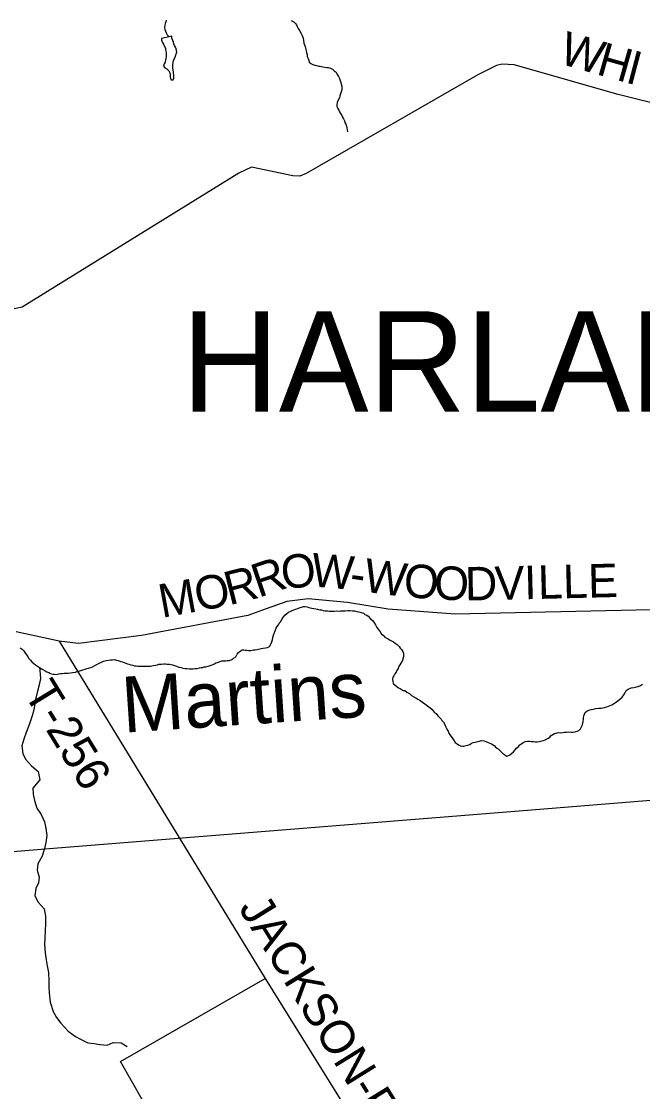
# Model space of a CAD drawing. Extents: x 1310247 to 1664935, y 284496 to 704931.
# Drawn here: x 1521928 to 1527488, y 468911 to 478494 of the extents above; entities that cross this region are included whole.
import ezdxf

# ---------------------------------------------------------------- set-up
doc = ezdxf.new("R2010")
doc.units = 0
for name, color, linetype in [('GM_X_Airport_Location_Class_2', 7, 'Continuous'), ('GM_X_County_Road_Text', 7, 'Continuous'), ('GM_X_County_Subdivision_Text', 7, 'Continuous'), ('GM_X_Minor_Lake_Text', 7, 'Continuous'), ('GM_X_Minor_River', 7, 'Continuous'), ('GM_X_Minor_River_Text', 7, 'Continuous'), ('GM_X_State_Route', 7, 'Continuous'), ('GM_X_Township_Road', 7, 'Continuous'), ('GM_X_Township_Subdivision', 7, 'Continuous')]:
    doc.layers.add(name, color=color, linetype=linetype)

msp = doc.modelspace()

# ---------------------------------------------------------------- linework, layer by layer
at = {"layer": 'GM_X_County_Road_Text'}
for points in [[(1527736.4, 477723.4), (1527268.2, 477838.9), (1526338.4, 478104.1), (1526232, 478109.7), (1526181.6, 478098.5), (1526013.6, 478014.9), (1524475.3, 477132.2), (1524418.6, 477107), (1524356.4, 477110), (1523988.1, 477187.9), (1523872.7, 477135.5), (1521933.8, 475934.2), (1521863.3, 475919.2)], [(1529754.6, 471722.4), (1529016.4, 472240.5), (1527703.6, 473187.4), (1527659.8, 473216.1), (1527563.6, 473225.7), (1525811.4, 473184.7), (1525209.6, 473232.1), (1524847, 473289.8), (1524496, 473323.4), (1524304.8, 473298.2), (1524119, 473232.9), (1523953.3, 473173.3), (1523002.5, 472995.5), (1522438.9, 472922.1), (1522264.5, 472942.8), (1521880.2, 473029)]]:
    msp.add_lwpolyline(points, dxfattribs=at)
at = {"layer": 'GM_X_County_Subdivision_Text'}
for points in [[(1522264.5, 472942.8), (1524109.1, 469924), (1526335.9, 466341.4)], [(1523319, 469469.4), (1524109.1, 469924)], [(1519694.9, 466699.1), (1522985.1, 468700), (1523036.2, 468753.3), (1523011.4, 468833.9), (1522816, 469179.9), (1523318.3, 469469), (1523319, 469469.4)]]:
    msp.add_lwpolyline(points, dxfattribs=at)
at = {"layer": 'GM_X_Minor_River'}
for points in [[(1523250.7, 478355.1), (1523180.5, 478340.8)], [(1523180.5, 478340.8), (1523182.1, 478324.7), (1523189.7, 478306.5), (1523199.3, 478290.2), (1523205, 478276), (1523216.5, 478253.6), (1523218.2, 478239.6), (1523223.6, 478215.3), (1523223.2, 478201.3), (1523222.7, 478179.2), (1523220.2, 478161.2), (1523217.9, 478147.3), (1523213.4, 478129.3), (1523207, 478115.4), (1523198.5, 478093.5), (1523212.1, 478077.2), (1523230, 478068.7), (1523247.6, 478050.2), (1523255.2, 478034), (1523258.9, 478017.9), (1523260.4, 477997.8), (1523262, 477983.7), (1523269.7, 477969.5), (1523285.8, 477971.1), (1523292.2, 477987), (1523290.8, 478009.1), (1523289.3, 478029.2), (1523289.6, 478043.2), (1523285.9, 478057.3), (1523284.3, 478073.4), (1523284.7, 478089.5), (1523283.3, 478111.6), (1523285.6, 478125.6), (1523290.1, 478143.5), (1523298.5, 478159.4), (1523302.9, 478175.3), (1523309.4, 478193.2), (1523318, 478217.1)], [(1523318, 478217.1), (1523316.4, 478233.2), (1523312.8, 478247.3), (1523307.1, 478263.5), (1523299.5, 478277.7), (1523291.8, 478294), (1523288.2, 478308.1), (1523282.5, 478324.3), (1523275, 478342.5), (1523273.4, 478360.6), (1523250.7, 478355.1)]]:
    msp.add_lwpolyline(points, dxfattribs=at)
at = {"layer": 'GM_X_Minor_River_Text'}
for points in [[(1523224.7, 478504.3), (1523220.4, 478490.3), (1523214, 478474.4), (1523211.6, 478458.4), (1523209.1, 478440.4), (1523210.7, 478422.3), (1523216.3, 478406.1), (1523224, 478391.9), (1523231.5, 478373.7), (1523250.7, 478355.1)], [(1524341.7, 478503.4), (1524365.4, 478490.8), (1524381.2, 478476.4), (1524390.8, 478462.1), (1524396.5, 478447.9), (1524404.2, 478431.7), (1524417.8, 478413.3), (1524431.2, 478386.9), (1524440.7, 478366.6), (1524446.4, 478352.4), (1524451.7, 478326.2), (1524457.1, 478298), (1524466.4, 478269.7), (1524470.1, 478255.5), (1524477.5, 478229.3), (1524479.1, 478215.2), (1524484.7, 478197), (1524486.3, 478180.9), (1524493.9, 478162.7), (1524499.5, 478144.5), (1524503.1, 478130.3), (1524518.8, 478115.9), (1524536.8, 478109.5), (1524554.7, 478103), (1524568.6, 478098.7), (1524588.6, 478094.2), (1524602.6, 478091.8), (1524624.6, 478087.3), (1524644.6, 478084.8), (1524660.6, 478082.4), (1524674.6, 478080), (1524694.6, 478075.6), (1524712.5, 478067.1), (1524726.2, 478052.7), (1524743.9, 478038.3), (1524755.5, 478017.9), (1524767.1, 477999.6), (1524774.6, 477981.3)], [(1524774.6, 477981.3), (1524780.3, 477965.1), (1524787.8, 477946.9), (1524789.5, 477932.8), (1524795.1, 477914.6), (1524796.7, 477898.5), (1524796.3, 477882.5), (1524789.8, 477862.6), (1524785.3, 477844.6), (1524778.8, 477826.7), (1524774.4, 477810.8), (1524766, 477796.9), (1524759.7, 477783), (1524755.3, 477769.1), (1524750.8, 477751.2), (1524752.4, 477733), (1524760, 477714.8), (1524767.6, 477698.6), (1524775.3, 477684.3), (1524785, 477670.1), (1524794.6, 477651.8), (1524802.2, 477637.5), (1524809.9, 477621.3), (1524819.5, 477605), (1524823.1, 477588.9), (1524830.8, 477574.7), (1524836.3, 477554.5), (1524840, 477540.3), (1524843.6, 477524.2), (1524845.2, 477506.1)], [(1522846.4, 472754.7), (1522862.3, 472748.3), (1522876.2, 472741.9), (1522890.2, 472739.6), (1522906.1, 472733.2), (1522926.1, 472728.7), (1522940, 472724.3), (1522954.1, 472724), (1522970.1, 472721.6), (1522990.1, 472719.1), (1523016.2, 472720.5), (1523032.3, 472720.1), (1523050.4, 472719.7), (1523066.4, 472719.3), (1523082.6, 472720.9), (1523096.7, 472722.6), (1523110.8, 472726.2), (1523129, 472729.8), (1523145.1, 472733.5), (1523159.3, 472737.1), (1523181.4, 472738.6), (1523201.6, 472740.1), (1523217.7, 472741.7), (1523233.7, 472739.3), (1523253.8, 472738.9), (1523279.7, 472732.2), (1523297.7, 472727.8), (1523315.5, 472719.3), (1523335.5, 472712.8), (1523357.5, 472708.3), (1523373.4, 472703.9), (1523393.4, 472699.4), (1523409.4, 472699), (1523431.5, 472696.5), (1523445.5, 472696.1), (1523463.7, 472697.7), (1523479.8, 472699.3), (1523499.9, 472700.8), (1523522.1, 472704.3), (1523536.2, 472708), (1523550.3, 472709.6), (1523564.5, 472713.3), (1523578.6, 472715), (1523598.8, 472720.5), (1523617, 472726.1), (1523635.3, 472733.7), (1523649.5, 472739.4), (1523667.8, 472749), (1523684, 472754.6), (1523706.3, 472762.1), (1523720.5, 472767.8), (1523734.6, 472769.4), (1523756.7, 472768.9), (1523770.8, 472770.5), (1523790.9, 472772.1), (1523811.2, 472779.6), (1523825.6, 472791.3), (1523846, 472804.8), (1523858.6, 472826.6), (1523871, 472842.4), (1523885.4, 472856.1), (1523903.8, 472865.7), (1523917.9, 472867.3), (1523933.9, 472864.9), (1523947.9, 472862.6), (1523961.9, 472860.2), (1523980, 472861.8), (1524004.2, 472865.2), (1524020.3, 472866.9), (1524038.5, 472870.4), (1524060.7, 472875.9), (1524074.9, 472879.6), (1524093, 472881.2), (1524111.2, 472884.7), (1524129.3, 472888.3), (1524147.6, 472897.9), (1524160.2, 472917.7), (1524168.8, 472939.5), (1524175.2, 472957.4), (1524179.8, 472977.4), (1524184.3, 472999.4), (1524190.8, 473015.2), (1524197.1, 473029.1), (1524201.5, 473045.1), (1524208, 473061), (1524216.4, 473076.8), (1524228.8, 473090.6), (1524235.2, 473104.5), (1524247.6, 473118.2), (1524258.1, 473138), (1524268.5, 473153.8), (1524287.2, 473177.5), (1524303.7, 473193.1), (1524318, 473202.8), (1524332.2, 473210.5), (1524352.5, 473218), (1524366.7, 473223.7), (1524380.9, 473229.4), (1524401.2, 473236.9), (1524421.5, 473244.5), (1524435.7, 473250.1)], [(1524435.7, 473250.1), (1524451.8, 473253.8), (1524467.9, 473253.4), (1524485.9, 473250.9), (1524499.9, 473246.6), (1524513.9, 473244.2), (1524527.8, 473239.9), (1524563.8, 473233), (1524577.8, 473230.7), (1524599.8, 473226.1), (1524613.8, 473223.8), (1524629.8, 473219.4), (1524647.8, 473216.9), (1524667.8, 473214.4), (1524681.8, 473212.1), (1524703.9, 473211.6), (1524728, 473213), (1524752.2, 473214.4), (1524772.3, 473213.9), (1524786.4, 473215.6), (1524804.4, 473215.2), (1524826.6, 473216.6), (1524850.7, 473218.1), (1524868.8, 473217.6), (1524890.8, 473215.1), (1524908.9, 473214.6), (1524928.9, 473210.2), (1524946.9, 473207.7), (1524968.8, 473201.2), (1524988.7, 473194.7), (1525002.5, 473184.3), (1525018.4, 473175.9), (1525032.3, 473167.5), (1525053.7, 473143), (1525071.4, 473128.5), (1525083.1, 473114.1), (1525096.6, 473091.7), (1525110, 473065.3), (1525121.7, 473051), (1525139.3, 473028.5), (1525150.8, 473008.2), (1525164.6, 472997.8), (1525182.2, 472979.3), (1525212, 472964.6), (1525227.8, 472952.1), (1525241.7, 472945.8), (1525259.5, 472937.3), (1525273.3, 472927), (1525291.1, 472914.5), (1525308.7, 472896), (1525318.4, 472881.7), (1525334.1, 472867.3), (1525341.7, 472851.1), (1525347.4, 472836.9), (1525349, 472820.8), (1525348.7, 472806.8), (1525342.1, 472786.9), (1525337.7, 472770.9), (1525325.1, 472747.1), (1525314.7, 472733.3), (1525304.1, 472713.5), (1525299.8, 472699.6), (1525289.3, 472681.8), (1525282.9, 472665.9), (1525270.5, 472652.1), (1525262, 472634.3), (1525253.6, 472620.5), (1525249.2, 472602.5), (1525252.7, 472582.3), (1525256.3, 472566.2), (1525270, 472553.8), (1525289.7, 472537.3), (1525303.5, 472527), (1525319.4, 472520.5), (1525345.1, 472503.9), (1525359.1, 472501.5), (1525378.8, 472487), (1525400.6, 472474.5), (1525420.3, 472457.9), (1525440.1, 472445.4), (1525457.9, 472436.9), (1525475.7, 472424.5), (1525497.5, 472411.9), (1525519.2, 472397.3), (1525539, 472382.8), (1525562.6, 472366.2), (1525586.3, 472347.6), (1525604, 472331.1), (1525623.5, 472308.6), (1525639.2, 472296.1), (1525654.8, 472275.7), (1525668.6, 472263.3), (1525684.2, 472246.9), (1525691.9, 472232.7), (1525705.6, 472218.3), (1525717.1, 472198), (1525726.6, 472175.6), (1525736.2, 472157.4), (1525747.8, 472139), (1525753.4, 472120.8), (1525770.8, 472094.3)], [(1521915.5, 472883.5), (1521933.3, 472873), (1521948.9, 472856.6), (1521958.6, 472842.3), (1521972.2, 472821.9), (1521983.9, 472807.6), (1521991.5, 472791.3), (1522009.2, 472774.9), (1522020.9, 472760.5), (1522038.5, 472744), (1522054.3, 472731.6), (1522072.1, 472719.2), (1522089.9, 472708.7), (1522119.5, 472689.9), (1522139.3, 472677.4), (1522155.2, 472669), (1522173.1, 472662.6), (1522189, 472656.2), (1522210.9, 472649.6), (1522225, 472649.3), (1522241, 472646.9), (1522263.2, 472652.4), (1522277.4, 472654), (1522293.5, 472655.6), (1522311.6, 472657.2), (1522327.6, 472656.8), (1522345.7, 472656.4), (1522367.9, 472659.9), (1522384, 472663.5), (1522412.3, 472666.8), (1522432.5, 472674.4), (1522450.8, 472680), (1522477.1, 472687.3), (1522497.3, 472692.9), (1522513.5, 472698.5), (1522529.6, 472702.1), (1522547.9, 472707.7), (1522564.1, 472715.3), (1522584.5, 472726.9), (1522602.8, 472736.5), (1522625.2, 472746), (1522643.5, 472755.6), (1522663.8, 472765.1), (1522686, 472770.6), (1522708.2, 472774.1), (1522724.4, 472777.7), (1522742.5, 472777.3), (1522760.6, 472778.8), (1522778.5, 472774.4), (1522794.6, 472772), (1522814.4, 472763.5), (1522832.4, 472759), (1522846.4, 472754.7)], [(1522089.9, 472708.7), (1522092.8, 472682), (1522099.4, 472609.5), (1522088.2, 472553.5), (1522068.7, 472485.6), (1522053.4, 472421.6), (1522039.5, 472329.5), (1522024.3, 472275.6), (1522000.7, 472203.8), (1521970.9, 472126), (1521949.6, 472066.2), (1521932.3, 472006.3), (1521941.1, 471939.8), (1521964.2, 471887.1), (1522019.5, 471827.8), (1522078.9, 471776.5), (1522091.6, 471703.9), (1522029.6, 471626.8), (1522032.6, 471574.5), (1522045.6, 471518.1), (1522066.4, 471447.4), (1522105.6, 471392.4), (1522134.6, 471325.5), (1522145.6, 471271.1), (1522154.3, 471204.7), (1522145, 471142.6), (1522135.9, 471086.5), (1522112.4, 471018.7), (1522074.7, 470951.2), (1522069.6, 470895), (1522086.5, 470830.4), (1522079.4, 470780.4), (1522056.2, 470728.6), (1522048.9, 470662.5), (1522078, 470605.7), (1522131.3, 470548.4), (1522142.1, 470481.9), (1522142.7, 470413.6), (1522141.6, 470353.4), (1522136.1, 470283.2), (1522135.1, 470231), (1522141.6, 470152.6), (1522150.5, 470090.1), (1522159.5, 470035.8), (1522170.4, 469977.3), (1522172.9, 469900.9), (1522173.9, 469848.7), (1522176.9, 469796.4), (1522185.3, 469711.9), (1522211.9, 469629.1), (1522243.1, 469574.2), (1522280.4, 469523.3), (1522347.5, 469451.7), (1522413.1, 469404.3), (1522468.9, 469373), (1522522.9, 469347.9), (1522579.2, 469342.8), (1522629.4, 469333.8), (1522695.8, 469326.5), (1522748.7, 469351.6), (1522821.2, 469346.1), (1522873, 469315)], [(1527410.9, 472530.3), (1527433.1, 472535.8), (1527449.3, 472539.4), (1527469.6, 472547), (1527488, 472560.6)], [(1525770.8, 472094.3), (1525782.4, 472078), (1525794.1, 472061.7), (1525811.6, 472037.2), (1525827.3, 472024.7), (1525841.2, 472016.4), (1525859, 472007.9), (1525875, 472003.5), (1525889.1, 472003.2), (1525909.3, 472008.7), (1525923.4, 472012.4), (1525941.7, 472020), (1525958, 472029.6), (1525972.3, 472037.3), (1525988.4, 472040.9), (1526012.7, 472046.4), (1526026.8, 472050), (1526047, 472053.6), (1526069, 472051), (1526085, 472046.6), (1526106.9, 472038.1), (1526120.8, 472031.7), (1526134.7, 472025.4), (1526158.4, 472008.7), (1526178, 471988.2), (1526195.8, 471979.8), (1526217.4, 471959.2), (1526235.1, 471942.7), (1526250.8, 471928.2), (1526268.5, 471915.8), (1526282.7, 471917.5), (1526299, 471927.1), (1526315.3, 471938.7), (1526331.8, 471954.4), (1526346.2, 471970.1), (1526360.7, 471985.8), (1526377.2, 472001.5), (1526389.6, 472017.2), (1526405.9, 472026.8), (1526420.2, 472036.5), (1526440.6, 472046.1), (1526458.7, 472047.6), (1526476.8, 472049.2), (1526490.8, 472046.9), (1526510.8, 472044.4), (1526526.9, 472044), (1526545, 472043.6), (1526561.1, 472047.2), (1526587.3, 472050.6), (1526601.5, 472056.2), (1526615.7, 472061.9), (1526642.2, 472075.3), (1526658.5, 472085), (1526668.9, 472098.8), (1526685.2, 472108.4), (1526699.5, 472118.1), (1526713.6, 472121.8), (1526731.8, 472125.3), (1526751.9, 472124.8), (1526774, 472126.3), (1526790.1, 472127.9), (1526808.3, 472129.5), (1526824.4, 472131.1), (1526848.5, 472130.5), (1526862.5, 472130.2), (1526884.7, 472133.7), (1526900.9, 472139.3), (1526917.1, 472145), (1526931.5, 472158.6), (1526940.1, 472178.5), (1526950.5, 472196.3), (1526952.9, 472210.3), (1526955.3, 472226.3), (1526957.7, 472242.3), (1526960.1, 472258.3), (1526962.6, 472276.3), (1526967, 472290.2), (1526973.4, 472306.1), (1526989.7, 472317.8), (1527008, 472325.3), (1527028.2, 472330.9), (1527048.4, 472334.4), (1527070.7, 472339.9), (1527096.9, 472343.3), (1527117, 472344.8), (1527131.1, 472348.5), (1527147.2, 472350.1), (1527167.5, 472357.6), (1527183.7, 472361.2), (1527212.1, 472374.6), (1527228.5, 472384.2), (1527246.8, 472393.8), (1527265.2, 472409.4), (1527283.7, 472425), (1527304.2, 472442.6), (1527320.9, 472464.3), (1527331.4, 472484.1), (1527341.9, 472501.9), (1527358.2, 472513.5), (1527386.7, 472524.9), (1527410.9, 472530.3)]]:
    msp.add_lwpolyline(points, dxfattribs=at)
at = {"layer": 'GM_X_State_Route'}
msp.add_lwpolyline([(1520768.9, 470972.3), (1522141.1, 471084.5), (1526494.6, 471433.2), (1529767.9, 471699.4), (1530589, 471768.1), (1532683.4, 471935.7), (1534976.7, 472122.2), (1536713.1, 472261.5), (1538630.6, 472415.9), (1541846.2, 472676.5), (1542038.7, 472693.8), (1542166.5, 472707.4), (1542260.5, 472718.7), (1542367.3, 472732.2), (1542517.7, 472754.7), (1542686.1, 472781.8), (1542816.9, 472803.6)], dxfattribs=at)

# ---------------------------------------------------------------- texts
at = {"layer": 'GM_X_Airport_Location_Class_2'}
msp.add_text('HARLAN', height=900, rotation=0.00001, dxfattribs=at).set_placement((1523363.5, 474999.1))
at = {"layer": 'GM_X_Minor_Lake_Text'}
msp.add_text('Martins', height=499.98, rotation=3.82536, dxfattribs=at).set_placement((1522841.2, 472124.1))
at = {"layer": 'GM_X_Township_Road'}
for s, rotation, p in [('W', 343.71257, (1526728.5, 478121.1)), ('H', 344.16915, (1527064.6, 478022.9)), ('I', 345.26279, (1527324.6, 477949.2)), ('O', 6.16078, (1524266.6, 473407.7)), ('W', 355.12769, (1524513.9, 473435.9)), ('R', 14.34565, (1523787.2, 473263.6)), ('R', 18.83218, (1524050.5, 473332)), ('W', 352.39331, (1524979.9, 473389.6)), ('O', 355.39047, (1525341.5, 473341.7)), ('O', 357.54179, (1525616.9, 473319.7)), ('D', 0.91627, (1525900, 473308.1)), ('V', 1.43853, (1526166.9, 473312.4)), ('I', 1.43639, (1526430.8, 473319.1)), ('L', 1.43605, (1526554, 473322.1)), ('L', 1.43605, (1526778.3, 473327.8)), ('E', 1.43605, (1527002.6, 473333.4)), ('O', 10.55221, (1523506.5, 473210.6)), ('-', 352.05976, (1524856, 473406.8)), ('M', 10.33443, (1523185, 473151.9))]:
    msp.add_text(s, height=300, rotation=rotation, dxfattribs=at).set_placement(p)
at = {"layer": 'GM_X_Township_Subdivision'}
for s, rotation, p in [('T-256', 301.44255, (1521943.5, 472478.2)), ('JACKSON-RUNYAN', 301.79027, (1523866.5, 470553))]:
    msp.add_text(s, height=300, rotation=rotation, dxfattribs=at).set_placement(p)

doc.saveas('drawing.dxf')
